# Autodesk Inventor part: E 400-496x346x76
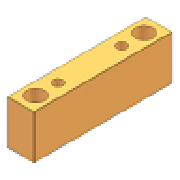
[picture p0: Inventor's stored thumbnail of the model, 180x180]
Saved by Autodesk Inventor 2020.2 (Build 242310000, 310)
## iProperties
Manager: www.cadconsulting.pl
Company: Fabian Stasiak CAD Consulting
Created: 2014-02
Part Number: E 400-496x346x76
Material: S 55 C
Description: Spacer Block
Document SubType Name: Modeling
Designer: F.Stasiak
Standard Revision: 1
Manufacturer: DME
Language: pl-PL
Size Designation: 496x346x76
Categories: <MemberInstance><Categories><Category DisplayName="Forma wtryskowa" InternalName="349578f2-f4d4-4954-8c09-8e99297a61c0" Mnemonic="MOLD"><Category DisplayName="P
Density: 7.85 g/cm^3
Appearance: Orange (Pale)
Catalog Web Link: www.expertbooks.pl
IsCustomPart: 1
Author: F.Stasiak
Subject: Zbiór ćwiczeń. Autodesk Inventor 2020. Kurs Professional
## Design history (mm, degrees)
sketch "Sketch1"
  geometry: L1 (-111, 248)-(-173, 248); L2 (-173, 248)-(-173, -248); L3 (-173, -248)-(-111, -248); L4 (-111, -248)-(-111, 248); L5 (173, 248)-(173, -248); L6 (111, -248)-(111, 248); L7 (111, 248)-(173, 248); L8 (111, -248)-(173, -248); 7 further points
  constraints: 16 end point, 3 parallel, 2 horizontal alignment, 2 midpoint, 2 perpendicular, 1 horizontal, 1 vertical
  dimensions: "d85" = 496 distance between parallel lines of L3 L1 (= L); "d86" = 62 distance between parallel lines of L4 L2 (= W_); "d88" = 62 distance between parallel lines of L5 L6 (= W_); "d89" = 173 distance from line of point (0, 0) L2 (= 0.5 x M_W); "d93" = 496 distance between parallel lines of L8 L7 (= L); "d94" = 173 distance from line of point (0, 0) L5 (= 0.5 x M_W); "d98" = 165 vertical distance of point (-137, 165) point (0, 0) (= 0.5 x S1_L); "d100" = 137 horizontal distance of point (-137, 165) point (0, 0) (= 0.5 x S1_W); "d101" = 137 horizontal distance of point (137, 165) point (0, 0) (= 0.5 x S1_W); "d102" = 165 vertical distance of point (0, 0) point (137, 165) (= 0.5 x S1_L); "d103" = 137 horizontal distance of point (-137, 208) point (0, 0) (= 0.5 x LS_W); "d105" = 208 vertical distance of point (-137, 208) point (0, 0) (= 0.5 x LS_L); "d106" = 137 horizontal distance of point (0, 0) point (137, 208) (= 0.5 x LS_W); "d107" = 208 vertical distance of point (137, 208) point (0, 0) (= 0.5 x LS_L)
extrude "Extrusion1" new body sketch "Sketch1" distance "d20" = 76 (= H_); taper "d30" = 0 deg
extrude "Extrusion2" join sketch "Sketch1" distance "d95" = 76 (= H_); taper "d96" = 0 deg
hole "Hole1" sketch "Sketch1" diameter "d129" = 18 (= S1_d1); stored, may be unused: countersink angle "d133" = 90 deg, drill point angle "d135" = 0 deg; dims "d130" = 6, "d131" = 4, "d132" = 2, "d134" = 76 (= H_)
pattern_linear "Rectangular Pattern1" dims "d156" = 330 (computed from S1_L, Ns)
hole "Hole2" sketch "Sketch1" diameter "d108" = 42 (= LS_d); stored, may be unused: countersink angle "d112" = 90 deg, drill point angle "d114" = 0 deg; dims "d109" = 6, "d110" = 4, "d111" = 2, "d113" = 76 (= H_)
pattern_linear "Rectangular Pattern2" dims "d138" = 416 (computed from LS_L, Nl)
hole "Hole3" sketch "Sketch1" diameter "d122" = 18 (= S1_d1); stored, may be unused: countersink angle "d126" = 90 deg, drill point angle "d128" = 0 deg; dims "d123" = 6, "d124" = 4, "d125" = 2, "d127" = 76 (= H_)
pattern_linear "Rectangular Pattern3" dims "d153" = 330 (computed from S1_L, Ns)
hole "Hole4" sketch "Sketch1" diameter "d115" = 42 (= LS_d); stored, may be unused: countersink angle "d119" = 90 deg, drill point angle "d121" = 0 deg; dims "d116" = 6, "d117" = 4, "d118" = 2, "d120" = 76 (= H_)
pattern_linear "Rectangular Pattern4" dims "d150" = 416 (computed from LS_L, Nl)
workplane "Work Plane1"
workplane "Work Plane2"
chamfer "Chamfer1" distance "d82" = 0.5; stored, may be unused: second distance "d83" = 2, angle "d84" = 45 deg
chamfer "Chamfer2" distance "d157" = 0.5; stored, may be unused: second distance "d158" = 2, angle "d159" = 45 deg
body "Solid1"
other parameters: "L" = 496 [user parameter; used in 2 equation terms], "W_" = 62 [user parameter; used in 2 equation terms], "H_" = 76 [user parameter; used in 7 equation terms], "M_W" = 346 [user parameter; used in 2 equation terms], "S1_W" = 274 [user parameter; used in 2 equation terms], "S1_d1" = 18 [user parameter; used in 2 equation terms], "LS_L" = 416 [user parameter; used in 4 equation terms], "LS_W" = 274 [user parameter; used in 2 equation terms], "LS_d" = 42 [user parameter; used in 2 equation terms], "d160" = 0, "d161" = 76 (= H_)
